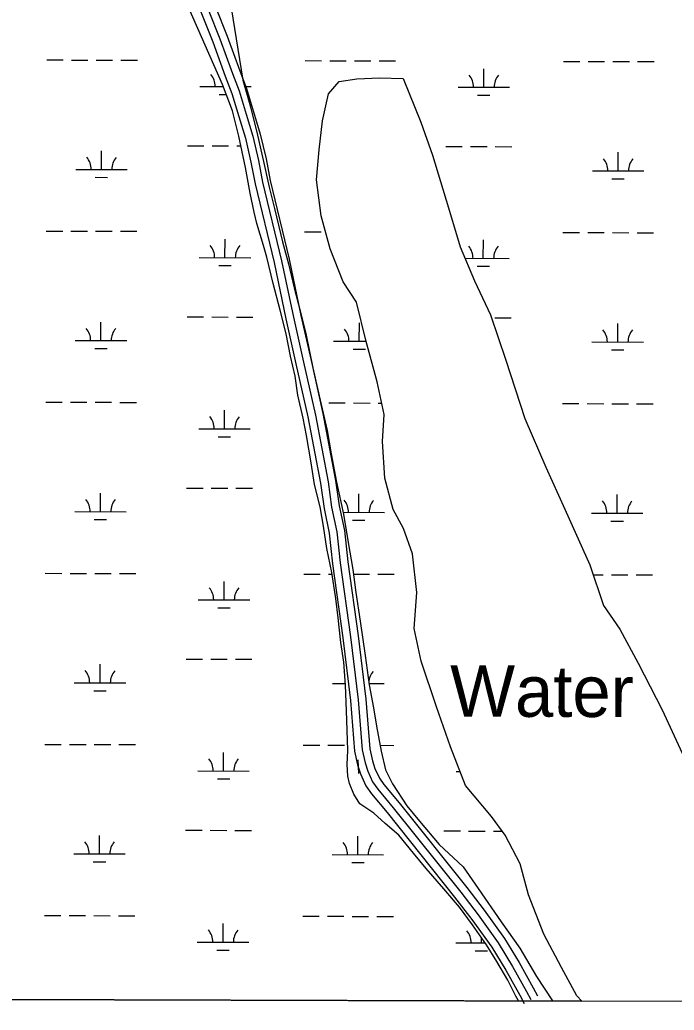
# Model space of a CAD drawing. Extents: x 3161615 to 3199515, y 867541 to 892976.
# Drawn here: x 3189678 to 3190949, y 872921 to 874846 of the extents above; entities that cross this region are included whole.
import ezdxf

# ---------------------------------------------------------------- set-up
doc = ezdxf.new("R2010")
doc.units = 0
for name, color, linetype in [('V-GRID-FRAM', 7, 'Continuous'), ('V-RIVR-IDEN', 7, 'Continuous'), ('V-ROAD-CNTR', 7, 'Continuous'), ('V-SITE-VEGE', 7, 'Continuous'), ('V-TOPO-SHOR', 7, 'Continuous'), ('V-WETL-SWMP', 7, 'Continuous')]:
    doc.layers.add(name, color=color, linetype=linetype)

msp = doc.modelspace()

# ---------------------------------------------------------------- linework, layer by layer
at = {"layer": 'V-GRID-FRAM'}
msp.add_lwpolyline([(3165877.4, 891195.5), (3197229, 891108.8), (3197186.7, 872920.9), (3165819.2, 873007.6), (3165877.4, 891195.5)], dxfattribs=at)
at = {"layer": 'V-ROAD-CNTR'}
msp.add_line((3190335, 873407.6), (3190335.8, 873381), dxfattribs=at)
for points in [[(3190029.9, 874861.6), (3190052.9, 874803.8), (3190077.2, 874736.9), (3190090.1, 874703.4), (3190103.6, 874658.6), (3190116.3, 874616.1), (3190127.1, 874569.9), (3190135.2, 874527.7), (3190172.2, 874374.4), (3190195, 874265.2), (3190214.7, 874177.6), (3190237.7, 874074.6), (3190262.1, 873945.8), (3190269.1, 873896.5), (3190279.2, 873848.6), (3190285.8, 873788.9), (3190305.9, 873645), (3190320.4, 873522.8), (3190328.4, 873424.7), (3190334.3, 873397.7), (3190340, 873380.1), (3190350.5, 873357.3), (3190361.5, 873341.3), (3190392, 873305), (3190522.9, 873140.8), (3190556.4, 873097.3), (3190594.9, 873043.7), (3190622.4, 872998.6), (3190649.2, 872949.9), (3190657.7, 872934.2)], [(3190044, 874866.6), (3190066.9, 874809.1), (3190091.3, 874742.2), (3190104.3, 874708.3), (3190117.9, 874662.9), (3190130.8, 874620), (3190141.8, 874573), (3190149.8, 874530.9), (3190186.8, 874377.7), (3190209.7, 874268.4), (3190229.4, 874180.9), (3190252.4, 874077.7), (3190276.9, 873948.2), (3190283.8, 873899.1), (3190294, 873851), (3190300.6, 873790.8), (3190320.8, 873647), (3190335.4, 873524.3), (3190343.3, 873426.9), (3190348.8, 873401.6), (3190354, 873385.5), (3190363.6, 873364.7), (3190373.5, 873350.4), (3190403.6, 873314.5), (3190534.7, 873150.1), (3190568.4, 873106.3), (3190607.4, 873052), (3190635.4, 873006.1), (3190662.3, 872957.1), (3190670.9, 872941.4)], [(3190058.1, 874871.7), (3190080.9, 874814.5), (3190105.3, 874747.4), (3190118.5, 874713.1), (3190132.3, 874667.3), (3190145.3, 874623.9), (3190156.5, 874576.1), (3190164.5, 874534), (3190201.4, 874381), (3190224.4, 874271.6), (3190244, 874184.2), (3190267.1, 874080.7), (3190291.7, 873950.7), (3190298.6, 873901.7), (3190308.8, 873853.3), (3190315.5, 873792.6), (3190335.7, 873648.9), (3190350.3, 873525.8), (3190358.2, 873429.1), (3190363.3, 873405.5), (3190368, 873391), (3190376.7, 873372.2), (3190385.4, 873359.5), (3190415.2, 873324), (3190546.5, 873159.3), (3190580.4, 873115.2), (3190619.9, 873060.3), (3190648.4, 873013.7), (3190675.5, 872964.3), (3190684.1, 872948.6)]]:
    msp.add_lwpolyline(points, dxfattribs=at)
at = {"layer": 'V-SITE-VEGE'}
for p, q in [((3190277.9, 874702.3), (3190298.3, 874726.2)), ((3190298.3, 874726.2), (3190332.7, 874731.9)), ((3190332.7, 874731.9), (3190377.1, 874733.8)), ((3190377.1, 874733.8), (3190422.8, 874732.5)), ((3190422.8, 874732.5), (3190457, 874647.4)), ((3190266.1, 874650), (3190277.9, 874702.3)), ((3190259.7, 874593.5), (3190266.1, 874650)), ((3190457, 874647.4), (3190480.1, 874583.3)), ((3190254.8, 874535), (3190259.7, 874593.5)), ((3190480.1, 874583.3), (3190511.2, 874481)), ((3190263.6, 874465.5), (3190254.8, 874535)), ((3190511.2, 874481), (3190533.4, 874404.7)), ((3190280.9, 874401.4), (3190263.6, 874465.5)), ((3190306.5, 874336.9), (3190280.9, 874401.4)), ((3190533.4, 874404.7), (3190561.3, 874339.1)), ((3190561.3, 874339.1), (3190592.4, 874272.9)), ((3190332.3, 874297.4), (3190306.5, 874336.9)), ((3190350.9, 874221.2), (3190332.3, 874297.4)), ((3190592.4, 874272.9), (3190622.3, 874184.7)), ((3190372.3, 874142.6), (3190350.9, 874221.2)), ((3190622.3, 874184.7), (3190658.9, 874071.4)), ((3190385.7, 874078.7), (3190372.3, 874142.6)), ((3190383, 874026.2), (3190385.7, 874078.7)), ((3190658.9, 874071.4), (3190699.9, 873976.9)), ((3190387.5, 873955.4), (3190383, 874026.2)), ((3190699.9, 873976.9), (3190737, 873894.8)), ((3190403.3, 873894.1), (3190387.5, 873955.4)), ((3190737, 873894.8), (3190785.4, 873786.8)), ((3190423.4, 873857.4), (3190403.3, 873894.1)), ((3190441, 873808.4), (3190423.4, 873857.4)), ((3190449.2, 873732.9), (3190441, 873808.4)), ((3190785.4, 873786.8), (3190811.9, 873707.6)), ((3190444.2, 873663), (3190449.2, 873732.9)), ((3190811.9, 873707.6), (3190843.8, 873661.8)), ((3190457.9, 873599.7), (3190444.2, 873663)), ((3190843.8, 873661.8), (3190879.7, 873595.6)), ((3190487.4, 873510.6), (3190457.9, 873599.7)), ((3190879.7, 873595.6), (3190925.7, 873505.1)), ((3190515.1, 873432.9), (3190487.4, 873510.6)), ((3190925.7, 873505.1), (3190972.9, 873403.9)), ((3190544, 873357.5), (3190515.1, 873432.9)), ((3190594.4, 873297.4), (3190544, 873357.5)), ((3190621.2, 873261.2), (3190594.4, 873297.4)), ((3190650.2, 873205.3), (3190621.2, 873261.2)), ((3190666.5, 873144.9), (3190650.2, 873205.3)), ((3190696.1, 873069), (3190666.5, 873144.9)), ((3190730.5, 873004.1), (3190696.1, 873069)), ((3190760.5, 872948.8), (3190730.5, 873004.1)), ((3189378.4, 872942.5), (3190770.1, 872938.6)), ((3190770.1, 872938.6), (3190760.5, 872948.8))]:
    msp.add_line(p, q, dxfattribs=at)
at = {"layer": 'V-TOPO-SHOR'}
for points in [[(3190350.9, 874221.2), (3190332.3, 874297.4), (3190306.5, 874336.9), (3190280.9, 874401.4), (3190263.6, 874465.5), (3190254.8, 874535), (3190259.7, 874593.5), (3190266.1, 874650), (3190277.9, 874702.3), (3190298.3, 874726.2), (3190332.7, 874731.9), (3190377.1, 874733.8), (3190422.8, 874732.5)], [(3190422.8, 874732.5), (3190457, 874647.4), (3190480.1, 874583.3), (3190511.2, 874481), (3190533.4, 874404.7), (3190561.3, 874339.1), (3190592.4, 874272.9), (3190622.3, 874184.7)], [(3190444.2, 873663), (3190449.2, 873732.9), (3190441, 873808.4), (3190423.4, 873857.4), (3190403.3, 873894.1), (3190387.5, 873955.4), (3190383, 874026.2), (3190385.7, 874078.7), (3190372.3, 874142.6), (3190350.9, 874221.2)], [(3190622.3, 874184.7), (3190658.9, 874071.4), (3190699.9, 873976.9), (3190737, 873894.8), (3190785.4, 873786.8), (3190811.9, 873707.6), (3190843.8, 873661.8), (3190879.7, 873595.6)], [(3190770.1, 872938.6), (3190760.5, 872948.8), (3190730.5, 873004.1), (3190696.1, 873069), (3190666.5, 873144.9), (3190650.2, 873205.3), (3190621.2, 873261.2), (3190594.4, 873297.4), (3190544, 873357.5), (3190515.1, 873432.9), (3190487.4, 873510.6), (3190457.9, 873599.7), (3190444.2, 873663)], [(3190879.7, 873595.6), (3190925.7, 873505.1), (3190972.9, 873403.9), (3191014.2, 873324.9), (3191053.4, 873231.2), (3191076.7, 873156.2), (3191100, 873034.2), (3191109.6, 872937.7)]]:
    msp.add_lwpolyline(points, dxfattribs=at)
at = {"layer": 'V-WETL-SWMP'}
for p, q in [((3190038.3, 875180.4), (3190111.5, 874728.9)), ((3190071.8, 874720.7), (3189987.7, 874912.5)), ((3189730.5, 874768.4), (3189762.5, 874768.3)), ((3189778.5, 874768.2), (3189810.5, 874768.1)), ((3189826.5, 874768.1), (3189858.5, 874768)), ((3189874.5, 874768), (3189906.5, 874767.9)), ((3190232.3, 874767), (3190264.3, 874766.9)), ((3190280.3, 874766.8), (3190312.3, 874766.7)), ((3190328.3, 874766.7), (3190360.3, 874766.6)), ((3190376.3, 874766.6), (3190408.3, 874766.5)), ((3190734.3, 874765.6), (3190766.3, 874765.5)), ((3190782.3, 874765.4), (3190814.3, 874765.4)), ((3190830.3, 874765.3), (3190862.3, 874765.2)), ((3190878.3, 874765.2), (3190910.3, 874765.1)), ((3190579.5, 874715.3), (3190579.6, 874751.3)), ((3190111.5, 874728.9), (3190126.2, 874676.9)), ((3190277.9, 874702.3), (3190298.3, 874726.2)), ((3190298.3, 874726.2), (3190332.7, 874731.9)), ((3190332.7, 874731.9), (3190377.1, 874733.8)), ((3190377.1, 874733.8), (3190422.8, 874732.5)), ((3190422.8, 874732.5), (3190457, 874647.4)), ((3190027.6, 874716.8), (3190073.3, 874716.7)), ((3190091.1, 874669.3), (3190071.8, 874720.7)), ((3190115, 874716.5), (3190127.6, 874716.5)), ((3190529.5, 874715.4), (3190629.5, 874715.1)), ((3190065.6, 874701.3), (3190079.1, 874701.2)), ((3190266.1, 874650), (3190277.9, 874702.3)), ((3190567.5, 874699.9), (3190591.5, 874699.8)), ((3190103.8, 874619.9), (3190091.1, 874669.3)), ((3190126.2, 874676.9), (3190140, 874622.1)), ((3190259.7, 874593.5), (3190266.1, 874650)), ((3190457, 874647.4), (3190480.1, 874583.3)), ((3190116.6, 874559.1), (3190103.8, 874619.9)), ((3190140, 874622.1), (3190151.4, 874570.8)), ((3189836.7, 874555.5), (3189836.8, 874591.5)), ((3190003.9, 874601.4), (3190035.9, 874601.3)), ((3190051.9, 874601.3), (3190083.9, 874601.2)), ((3190099.9, 874601.2), (3190107.7, 874601.1)), ((3190254.8, 874535), (3190259.7, 874593.5)), ((3190505.8, 874600), (3190537.8, 874599.9)), ((3190553.8, 874599.9), (3190585.8, 874599.8)), ((3190601.8, 874599.8), (3190633.8, 874599.7)), ((3190840.5, 874552.7), (3190840.6, 874588.7)), ((3190151.4, 874570.8), (3190162.5, 874520.9)), ((3190480.1, 874583.3), (3190511.2, 874481)), ((3189786.7, 874555.6), (3189886.7, 874555.3)), ((3190125.6, 874509.2), (3190116.6, 874559.1)), ((3190790.5, 874552.8), (3190890.5, 874552.5)), ((3189824.7, 874540.1), (3189848.7, 874540)), ((3190263.6, 874465.5), (3190254.8, 874535)), ((3190828.5, 874537.3), (3190852.5, 874537.2)), ((3190162.5, 874520.9), (3190172.8, 874479.7)), ((3190133.6, 874472.3), (3190125.6, 874509.2)), ((3190138.6, 874450.3), (3190133.6, 874472.3)), ((3190172.8, 874479.7), (3190188.5, 874414.9)), ((3190511.2, 874481), (3190533.4, 874404.7)), ((3190280.9, 874401.4), (3190263.6, 874465.5)), ((3189729.5, 874435.7), (3189761.5, 874435.6)), ((3189777.5, 874435.6), (3189809.5, 874435.5)), ((3189825.5, 874435.4), (3189857.5, 874435.3)), ((3189873.5, 874435.3), (3189905.5, 874435.2)), ((3190151.5, 874407.3), (3190138.6, 874450.3)), ((3190231.4, 874434.3), (3190263.4, 874434.2)), ((3190076.7, 874384), (3190076.8, 874420)), ((3190188.5, 874414.9), (3190199.9, 874371.7)), ((3190578.6, 874382.6), (3190578.7, 874418.6)), ((3190733.3, 874432.9), (3190765.3, 874432.8)), ((3190781.3, 874432.8), (3190813.3, 874432.7)), ((3190829.3, 874432.6), (3190861.3, 874432.5)), ((3190877.3, 874432.5), (3190909.3, 874432.4)), ((3190158.1, 874384.6), (3190151.5, 874407.3)), ((3190306.5, 874336.9), (3190280.9, 874401.4)), ((3190533.4, 874404.7), (3190561.3, 874339.1)), ((3190026.7, 874384.1), (3190126.7, 874383.8)), ((3190170.6, 874333.9), (3190158.1, 874384.6)), ((3190542.7, 874382.7), (3190628.6, 874382.5)), ((3190064.7, 874368.6), (3190088.7, 874368.5)), ((3190199.9, 874371.7), (3190211.3, 874325.5)), ((3190566.6, 874367.2), (3190590.6, 874367.1)), ((3190561.3, 874339.1), (3190592.4, 874272.9)), ((3190183.8, 874281.9), (3190170.6, 874333.9)), ((3190211.3, 874325.5), (3190223.5, 874277.9)), ((3190332.3, 874297.4), (3190306.5, 874336.9)), ((3190195.4, 874236.1), (3190183.8, 874281.9)), ((3190350.9, 874221.2), (3190332.3, 874297.4)), ((3190003, 874268.8), (3190035, 874268.7)), ((3190051, 874268.6), (3190083, 874268.5)), ((3190099, 874268.5), (3190131, 874268.4)), ((3190223.5, 874277.9), (3190234.7, 874233.2)), ((3190592.4, 874272.9), (3190622.3, 874184.7)), ((3190600.9, 874267.1), (3190632.9, 874267)), ((3189835.8, 874222.8), (3189835.9, 874258.8)), ((3190337.7, 874221.4), (3190337.8, 874257.4)), ((3190839.6, 874220), (3190839.7, 874256)), ((3189785.8, 874222.9), (3189885.8, 874222.6)), ((3190203.8, 874192.7), (3190195.4, 874236.1)), ((3190234.7, 874233.2), (3190247.3, 874170)), ((3189823.7, 874207.4), (3189847.7, 874207.3)), ((3190287.7, 874221.5), (3190350.9, 874221.4)), ((3190325.6, 874206), (3190349.6, 874205.9)), ((3190372.3, 874142.6), (3190350.9, 874221.2)), ((3190789.6, 874220.1), (3190889.6, 874219.9)), ((3190827.5, 874204.6), (3190851.5, 874204.5)), ((3190212.9, 874153.7), (3190203.8, 874192.7)), ((3190622.3, 874184.7), (3190658.9, 874071.4)), ((3190247.3, 874170), (3190259.9, 874115.3)), ((3190218.5, 874116.8), (3190212.9, 874153.7)), ((3190385.7, 874078.7), (3190372.3, 874142.6)), ((3190228.4, 874071.6), (3190218.5, 874116.8)), ((3190259.9, 874115.3), (3190275.1, 874048.1)), ((3189728.6, 874103), (3189760.6, 874102.9)), ((3189776.6, 874102.9), (3189808.6, 874102.8)), ((3189824.6, 874102.7), (3189856.6, 874102.7)), ((3189872.6, 874102.6), (3189904.6, 874102.5)), ((3190075.8, 874051.3), (3190075.9, 874087.3)), ((3190278.5, 874101.5), (3190310.5, 874101.4)), ((3190326.5, 874101.4), (3190358.5, 874101.3)), ((3190374.5, 874101.2), (3190381, 874101.2)), ((3190732.4, 874100.2), (3190764.4, 874100.1)), ((3190780.4, 874100.1), (3190812.4, 874100)), ((3190828.4, 874100), (3190860.4, 874099.9)), ((3190876.4, 874099.8), (3190908.4, 874099.7)), ((3190235.2, 874038.3), (3190228.4, 874071.6)), ((3190383, 874026.2), (3190385.7, 874078.7)), ((3190658.9, 874071.4), (3190699.9, 873976.9)), ((3190025.8, 874051.4), (3190125.8, 874051.2)), ((3190063.7, 874035.9), (3190087.7, 874035.8)), ((3190244.4, 873984.9), (3190235.2, 874038.3)), ((3190275.1, 874048.1), (3190282.7, 874002.4)), ((3190387.5, 873955.4), (3190383, 874026.2)), ((3190282.7, 874002.4), (3190293.1, 873947.6)), ((3190250.9, 873942.8), (3190244.4, 873984.9)), ((3190699.9, 873976.9), (3190737, 873894.8)), ((3190403.3, 873894.1), (3190387.5, 873955.4)), ((3190002.1, 873936.1), (3190034.1, 873936)), ((3190050.1, 873935.9), (3190082.1, 873935.9)), ((3190098.1, 873935.8), (3190130.1, 873935.7)), ((3190261.8, 873899.8), (3190250.9, 873942.8)), ((3190293.1, 873947.6), (3190306.7, 873885.1)), ((3189834.9, 873890.1), (3189835, 873926.1)), ((3190336.8, 873888.7), (3190336.9, 873924.7)), ((3190838.7, 873887.3), (3190838.8, 873923.3)), ((3190267.9, 873861.6), (3190261.8, 873899.8)), ((3190737, 873894.8), (3190785.4, 873786.8)), ((3189784.9, 873890.2), (3189884.9, 873890)), ((3190305.8, 873888.8), (3190386.8, 873888.6)), ((3190306.7, 873885.1), (3190315.9, 873830.3)), ((3190423.4, 873857.4), (3190403.3, 873894.1)), ((3190788.7, 873887.5), (3190888.7, 873887.2)), ((3189822.8, 873874.7), (3189846.8, 873874.6)), ((3190274.6, 873818.5), (3190267.9, 873861.6)), ((3190324.7, 873873.3), (3190348.7, 873873.3)), ((3190441, 873808.4), (3190423.4, 873857.4)), ((3190826.6, 873871.9), (3190850.6, 873871.9)), ((3190284.5, 873772), (3190274.6, 873818.5)), ((3190315.9, 873830.3), (3190324.9, 873777.7)), ((3190449.2, 873732.9), (3190441, 873808.4)), ((3190785.4, 873786.8), (3190811.9, 873707.6)), ((3189727.7, 873770.3), (3189759.7, 873770.2)), ((3189775.7, 873770.2), (3189807.7, 873770.1)), ((3189823.7, 873770.1), (3189855.7, 873770)), ((3189871.7, 873769.9), (3189903.7, 873769.8)), ((3190229.6, 873768.9), (3190261.6, 873768.9)), ((3190277.6, 873768.8), (3190284.9, 873768.8)), ((3190292.1, 873721.5), (3190284.5, 873772)), ((3190324.9, 873777.7), (3190331.1, 873732.8)), ((3190326.2, 873768.7), (3190357.6, 873768.6)), ((3190373.6, 873768.5), (3190405.6, 873768.5)), ((3190791.9, 873767.4), (3190811.5, 873767.3)), ((3190827.5, 873767.3), (3190859.5, 873767.2)), ((3190875.5, 873767.2), (3190907.5, 873767.1)), ((3190074.9, 873718.6), (3190075, 873754.6)), ((3190296.3, 873683.4), (3190292.1, 873721.5)), ((3190331.1, 873732.8), (3190339.6, 873677.3)), ((3190444.2, 873663), (3190449.2, 873732.9)), ((3190024.9, 873718.8), (3190124.9, 873718.5)), ((3190062.8, 873703.2), (3190086.8, 873703.2)), ((3190811.9, 873707.6), (3190843.8, 873661.8)), ((3190301.9, 873635.8), (3190296.3, 873683.4)), ((3190339.6, 873677.3), (3190349.2, 873610.6)), ((3190457.9, 873599.7), (3190444.2, 873663)), ((3190843.8, 873661.8), (3190879.7, 873595.6)), ((3190307.4, 873597.6), (3190301.9, 873635.8)), ((3190349.2, 873610.6), (3190357, 873553.2)), ((3189834, 873557.4), (3189834.1, 873593.4)), ((3190001.1, 873603.4), (3190033.1, 873603.3)), ((3190049.1, 873603.3), (3190081.1, 873603.2)), ((3190097.1, 873603.1), (3190129.1, 873603.1)), ((3190310.9, 873552.9), (3190307.4, 873597.6)), ((3190487.4, 873510.6), (3190457.9, 873599.7)), ((3190879.7, 873595.6), (3190925.7, 873505.1)), ((3189784, 873557.6), (3189884, 873557.3)), ((3190285.9, 873556.2), (3190310.7, 873556.1)), ((3190312.9, 873502.7), (3190310.9, 873552.9)), ((3190356.6, 873556), (3190385.8, 873555.9)), ((3190357, 873553.2), (3190365.3, 873508.8)), ((3189821.9, 873542), (3189845.9, 873542)), ((3190515.1, 873432.9), (3190487.4, 873510.6)), ((3190314.1, 873465.6), (3190312.9, 873502.7)), ((3190365.3, 873508.8), (3190371.2, 873473)), ((3190925.7, 873505.1), (3190972.9, 873403.9)), ((3190371.2, 873473), (3190380.3, 873424.7)), ((3190315.5, 873426), (3190314.1, 873465.6)), ((3189726.8, 873437.7), (3189758.8, 873437.6)), ((3189774.8, 873437.5), (3189806.8, 873437.4)), ((3189822.8, 873437.4), (3189854.8, 873437.3)), ((3189870.8, 873437.3), (3189902.8, 873437.2)), ((3190228.7, 873436.3), (3190260.7, 873436.2)), ((3190276.7, 873436.1), (3190308.7, 873436.1)), ((3190378.2, 873435.9), (3190404.7, 873435.8)), ((3190544, 873357.5), (3190515.1, 873432.9)), ((3190074, 873386), (3190074.1, 873422)), ((3190313.8, 873398.8), (3190315.5, 873426)), ((3190380.3, 873424.7), (3190388.5, 873388.4)), ((3190315.6, 873376), (3190313.8, 873398.8)), ((3190024, 873386.1), (3190124, 873385.8)), ((3190318.9, 873361.4), (3190315.6, 873376)), ((3190388.5, 873388.4), (3190402.2, 873361.1)), ((3190525.8, 873384.7), (3190533.6, 873384.7)), ((3190061.9, 873370.6), (3190085.9, 873370.5)), ((3190326.8, 873340.7), (3190318.9, 873361.4)), ((3190402.2, 873361.1), (3190429.7, 873318.4)), ((3190594.4, 873297.4), (3190544, 873357.5)), ((3190339, 873322), (3190326.8, 873340.7)), ((3190366, 873304.2), (3190339, 873322)), ((3190429.7, 873318.4), (3190454.7, 873288.3)), ((3190388, 873284.1), (3190366, 873304.2)), ((3190414.5, 873261.1), (3190388, 873284.1)), ((3190454.7, 873288.3), (3190492.6, 873243.3)), ((3190621.2, 873261.2), (3190594.4, 873297.4)), ((3189833, 873224.8), (3189833.1, 873260.8)), ((3190000.2, 873270.7), (3190032.2, 873270.6)), ((3190048.2, 873270.6), (3190080.2, 873270.5)), ((3190096.2, 873270.5), (3190128.2, 873270.4)), ((3190334.9, 873223.4), (3190335, 873259.4)), ((3190443.1, 873225.9), (3190414.5, 873261.1)), ((3190502.1, 873269.3), (3190534.1, 873269.3)), ((3190550.1, 873269.2), (3190582.1, 873269.1)), ((3190598.1, 873269.1), (3190615.4, 873269)), ((3190650.2, 873205.3), (3190621.2, 873261.2)), ((3190492.6, 873243.3), (3190539.4, 873199.3)), ((3189783, 873224.9), (3189883, 873224.6)), ((3190284.9, 873223.5), (3190384.9, 873223.2)), ((3190467.3, 873196.4), (3190443.1, 873225.9)), ((3189821, 873209.4), (3189845, 873209.3)), ((3190322.9, 873208), (3190346.9, 873207.9)), ((3190666.5, 873144.9), (3190650.2, 873205.3)), ((3190501.8, 873157.1), (3190467.3, 873196.4)), ((3190539.4, 873199.3), (3190568.3, 873157.2)), ((3190532.4, 873121.4), (3190501.8, 873157.1)), ((3190568.3, 873157.2), (3190613.5, 873092.5)), ((3190696.1, 873069), (3190666.5, 873144.9)), ((3190557.4, 873087.1), (3190532.4, 873121.4)), ((3189725.9, 873105), (3189757.9, 873104.9)), ((3189773.9, 873104.9), (3189805.9, 873104.8)), ((3189821.9, 873104.7), (3189853.9, 873104.6)), ((3189869.9, 873104.6), (3189901.9, 873104.5)), ((3190073, 873053.3), (3190073.1, 873089.3)), ((3190227.8, 873103.6), (3190259.8, 873103.5)), ((3190275.8, 873103.5), (3190307.8, 873103.4)), ((3190323.8, 873103.3), (3190355.8, 873103.2)), ((3190371.8, 873103.2), (3190403.8, 873103.1)), ((3190584.9, 873047.8), (3190557.4, 873087.1)), ((3190613.5, 873092.5), (3190649.4, 873041.3)), ((3190730.5, 873004.1), (3190696.1, 873069)), ((3190023, 873053.4), (3190123, 873053.1)), ((3190524.9, 873052), (3190582, 873051.9)), ((3190574.9, 873051.9), (3190575, 873062)), ((3190605.1, 873015.6), (3190584.9, 873047.8)), ((3190061, 873037.9), (3190085, 873037.8)), ((3190562.9, 873036.5), (3190586.9, 873036.4)), ((3190649.4, 873041.3), (3190682.1, 872986.7)), ((3190626.2, 872979.2), (3190605.1, 873015.6)), ((3190760.5, 872948.8), (3190730.5, 873004.1)), ((3190641.6, 872948.4), (3190626.2, 872979.2)), ((3190682.1, 872986.7), (3190713, 872938.8)), ((3189378.4, 872942.5), (3190647.2, 872938.9)), ((3190647.2, 872938.9), (3190641.6, 872948.4)), ((3190713, 872938.8), (3190770.1, 872938.6)), ((3190770.1, 872938.6), (3190760.5, 872948.8))]:
    msp.add_line(p, q, dxfattribs=at)
for centre, start, end in [((3190022.4, 874717.3), 359.0699, 40.6135), ((3190524.3, 874715.9), 359.0699, 40.6135), ((3190634.8, 874715.6), 139.0699, 180.6135), ((3189781.5, 874556.1), 359.0699, 40.6135), ((3189892, 874555.8), 139.0699, 180.6135), ((3190785.3, 874553.3), 359.0699, 40.6135), ((3190895.8, 874553), 139.0699, 180.6135), ((3190021.5, 874384.6), 359.0699, 40.6135), ((3190132, 874384.3), 139.0699, 180.6135), ((3190523.4, 874383.2), 359.0699, 40.6135), ((3190633.8, 874382.9), 139.0699, 180.6135), ((3189780.5, 874223.4), 359.0699, 40.6135), ((3189891, 874223.1), 139.0699, 180.6135), ((3190282.4, 874222), 359.0699, 40.6135), ((3190784.3, 874220.6), 359.0699, 40.6135), ((3190894.8, 874220.3), 139.0699, 180.6135), ((3190020.5, 874051.9), 359.0699, 40.6135), ((3190131, 874051.6), 139.0699, 180.6135), ((3189779.6, 873890.7), 359.0699, 40.6135), ((3189890.1, 873890.4), 139.0699, 180.6135), ((3190281.5, 873889.3), 359.0699, 40.6135), ((3190392, 873889), 139.0699, 180.6135), ((3190783.4, 873888), 359.0699, 40.6135), ((3190893.9, 873887.7), 139.0699, 180.6135), ((3190019.6, 873719.3), 359.0699, 40.6135), ((3190130.1, 873719), 139.0699, 180.6135), ((3189778.7, 873558.1), 359.0699, 40.6135), ((3189889.2, 873557.8), 139.0699, 180.6135), ((3190280.6, 873556.7), 36.426, 40.6135), ((3190391.1, 873556.4), 139.0699, 173.9766), ((3190018.7, 873386.6), 359.0699, 40.6135), ((3190129.2, 873386.3), 139.0699, 180.6135), ((3189777.8, 873225.4), 359.0699, 40.6135), ((3189888.3, 873225.1), 139.0699, 180.6135), ((3190279.7, 873224), 359.0699, 40.6135), ((3190390.2, 873223.7), 139.0699, 180.6135), ((3190017.8, 873053.9), 359.0699, 40.6135), ((3190128.3, 873053.6), 139.0699, 180.6135), ((3190519.7, 873052.5), 359.0699, 40.6135)]:
    msp.add_arc(centre, 35.2, start, end, dxfattribs=at)

# ---------------------------------------------------------------- texts
at = {"layer": 'V-RIVR-IDEN'}
msp.add_text('Water', height=100, rotation=359.8626, dxfattribs=at).set_placement((3190513.8, 873491.6))

doc.saveas('drawing.dxf')
